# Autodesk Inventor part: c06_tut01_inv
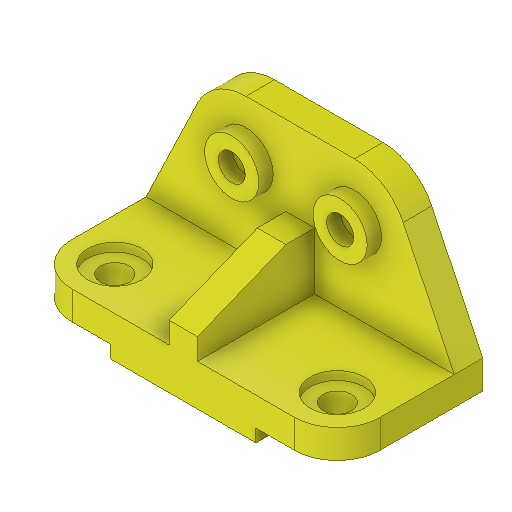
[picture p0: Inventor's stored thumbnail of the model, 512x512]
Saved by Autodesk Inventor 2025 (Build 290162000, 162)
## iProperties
Created: 2015-03
Part Number: c06_tut01_inv
Material: Generic
Document SubType Name: Modeling
Designer: Sandeep
Density: 1 g/cm^3
Appearance: Yellow
Author: Sandeep
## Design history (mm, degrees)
sketch "Sketch1"
  geometry: L1 (51, 0)-(51, 9); L2 (51, 9)-(108, 9); L3 (108, 9)-(108, 29); L4 (108, 29)-(-108, 29); L5 (-108, 29)-(-108, 9); L6 (-108, 9)-(-51, 9); L7 (-51, 9)-(-51, 0); L8 (-51, 0)-(51, 0); L9 (0, 96.725)-(0, -45.323); 1 further point
  constraints: 18 end point, 6 perpendicular, 3 point on line, 2 vertical, 1 midpoint, 2 other
  dimensions: "d1" = 20 distance of L2.end L3.end; "d2" = 57 distance between parallel lines of L5 L7; "d3" = 102 distance between parallel lines of L7 L1; "d66" = 9 distance between parallel lines of L2 L8
extrude "Extrusion1" new body sketch "Sketch1" distance "d4" = 102; taper "d5" = 0 deg
sketch "Sketch2"
  geometry: L1 (-108, -29)-(108, -29) reference; L2 (108, -29)-(72.256, -103.447); L3 (38, -125)-(-38, -125); L4 (-72.256, -103.447)-(-108, -29); L5 (0, -125)-(0, -29); L6 (51, 0)-(-51, 0) reference; A1 r 38 centre (38, -87) between (38, -125) and (72.256, -103.447); A2 r 38 centre (-38, -87) between (-72.256, -103.447) and (-38, -125); 2 further points
  constraints: 8 end point, 4 point on circle, 4 tangent, 3 midpoint, 2 centre point, 1 parallel, 1 point on line, 1 vertical, 2 other
  dimensions: "d6" = 96 distance between parallel lines of L1 L3; "d7" = 38 radius of A2; "d8" = 76 distance of L3.start L3.end
extrude "Extrusion2" join sketch "Sketch2" distance "d9" = 20; taper "d10" = 0 deg
sketch "Sketch3"
  geometry: L1 (0, 198.489)-(0, -42.784); L2 (38, 125)-(-38, 125) reference; C1 r 19 at (-38, 87); C2 r 9.5 at (-38, 87); C3 r 9.5 at (38, 87); C4 r 19 at (38, 87); 2 further points
  constraints: 4 centre point, 2 coincident, 2 end point, 2 equal radius, 1 midpoint, 1 point on line, 1 vertical, 2 other
  dimensions: "d11" = 38 diameter of C1; "d12" = 19 diameter of C2; "d13" = 76 distance of C3.centre C1.centre; "d14" = 38 distance from line of C1.centre L2
extrude "Extrusion3" join sketch "Sketch3" distance "d15" = 10; taper "d16" = 0 deg
fillet "Fillet1" dims "d17" = 30
sketch "Sketch5"
  geometry: A1 r 30 centre (186, -52) between (186, -82) and (216, -52) reference; 1 further point
  constraints: 1 coincident
hole "Hole3" sketch "Sketch5" at (186, -52) diameter "d38" = 20; stored, may be unused: countersink angle "d42" = 90 deg, drill point angle "d44" = 118 deg; dims "d39" = 6, "d40" = 38, "d41" = 6, "d43" = 8
hole "Hole4" diameter "d47" = 20; stored, may be unused: countersink angle "d51" = 90 deg, drill point angle "d53" = 118 deg; dims "d45" = 10, "d46" = 10, "d48" = 6, "d49" = 38, "d50" = 6, "d52" = 8
workplane "Work Plane1"
sketch "Sketch4"
  geometry: L1 (-40, 0.112)-(-40, -20); L2 (-40, -20)-(-15, -82); L3 (20, -82)-(0, -82) reference; L4 (-15, -82)-(0, -82); L5 (0, -52)-(0, 0) reference; L6 (-96, 0)-(-74.447, 0) reference; 1 further point
  constraints: 6 end point, 1 collinear, 1 vertical
  dimensions: "d55" = 40 distance between parallel lines of L1 L5; "d56" = 20 distance from line of L6 L1.end; "d57" = 15 distance of L2.end L3.end
feature "Rib1" sketch "Sketch4" dims "d58" = 1, "d59" = 20, "d60" = 0, "d61" = 0, "d62" = 1, "d63" = 1
body "Solid1"
other parameters: "d54" = -108
